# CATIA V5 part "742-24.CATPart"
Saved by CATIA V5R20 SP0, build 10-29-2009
Part number: 742-24
Bounding box of the stored display mesh (mm): x -24 to 25, y -23.94 to 23.94, z -23 to 56
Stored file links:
  C:\Users\Utente\Desktop\IO LAVORO\3D X SITO CF\X SITO\742\742-24.CATPart
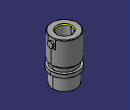
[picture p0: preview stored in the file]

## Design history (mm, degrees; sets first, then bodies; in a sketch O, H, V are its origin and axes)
Set1
  DatumSurface1 to DatumSurface38 "742-24"
Body1 (main body)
